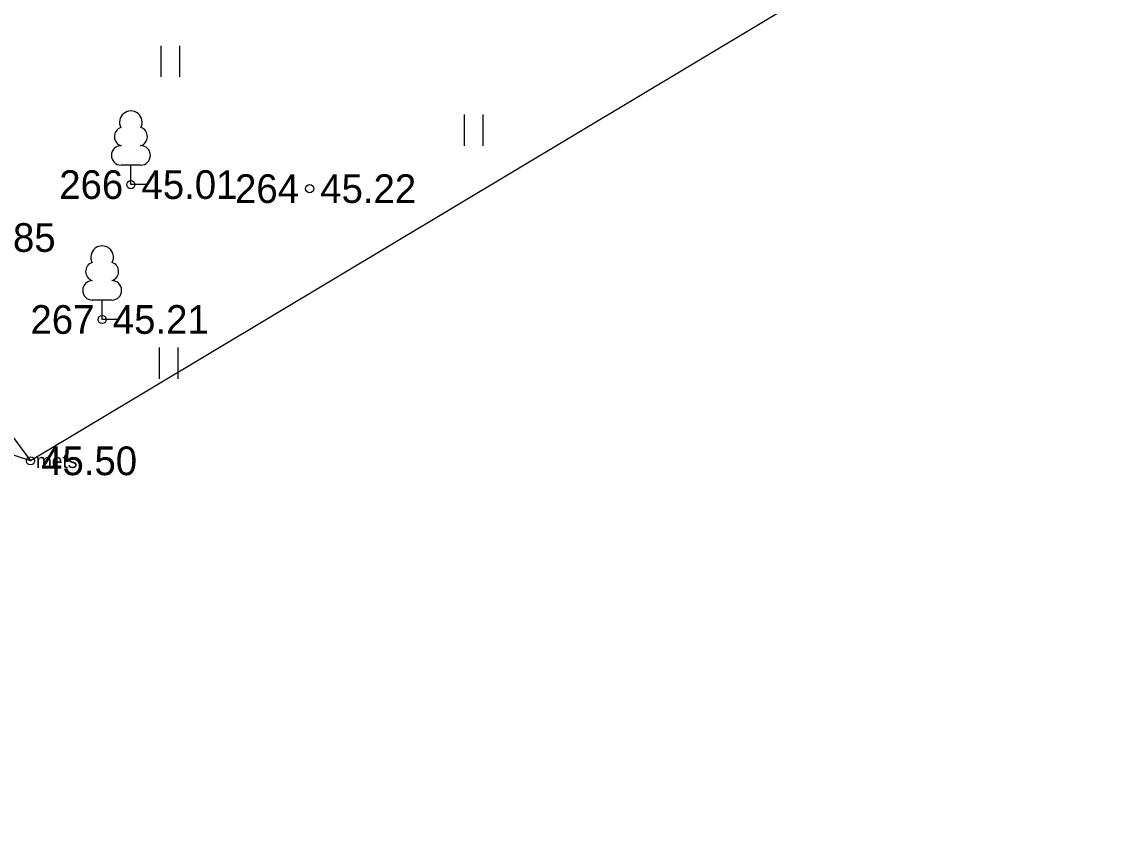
# Model space of a CAD drawing. Extents: x 505800 to 507326, y 6540058 to 6542128.
# Drawn here: x 506360.03 to 506386.44, y 6540313.38 to 6540333.29 of the extents above; entities that cross this region are included whole.
import ezdxf

# ---------------------------------------------------------------- set-up
doc = ezdxf.new("R2010")
doc.units = 0
for name, color, linetype in [('HALJASTUS', 7, 'Continuous'), ('KORGUS-EH2000', 7, 'Continuous'), ('MAAMUDEL', 7, 'Continuous'), ('MOOTKORG-EH2000', 7, 'Continuous'), ('MOOTMPUNKT', 7, 'Continuous'), ('MOOTNR', 7, 'Continuous'), ('MOOTPIIR', 7, 'Continuous'), ('PUU', 7, 'Continuous')]:
    doc.layers.add(name, color=color, linetype=linetype)

msp = doc.modelspace()

# ---------------------------------------------------------------- linework, layer by layer
at = {"layer": 'HALJASTUS'}
for p, q in [((506363.43, 6540332.702), (506363.43, 6540331.941)), ((506363.885, 6540332.702), (506363.885, 6540331.941)), ((506370.837, 6540331.019), (506370.837, 6540330.258)), ((506371.292, 6540331.019), (506371.292, 6540330.258)), ((506363.39, 6540325.331), (506363.39, 6540324.57)), ((506363.845, 6540325.331), (506363.845, 6540324.57))]:
    msp.add_line(p, q, dxfattribs=at)
msp.add_lwpolyline([(506306.227, 6540291.97), (506307.537, 6540296.92), (506309.208, 6540301.088), (506313.28, 6540303.838), (506321.716, 6540309.454), (506329.329, 6540313.144), (506334.711, 6540318.885), (506344.435, 6540326.129), (506351.88, 6540331.712), (506354.071, 6540331.501), (506356.847, 6540327.167), (506360.247, 6540322.568)], dxfattribs=at)
at = {"layer": 'KORGUS-EH2000'}
for centre in [(506362.697, 6540329.311), (506367.061, 6540329.212), (506361.996, 6540326.018), (506360.247, 6540322.568)]:
    msp.add_circle(centre, 0.1, dxfattribs=at)
at = {"layer": 'MOOTMPUNKT'}
for centre in [(506362.697, 6540329.311), (506367.061, 6540329.212), (506361.996, 6540326.018), (506360.247, 6540322.568)]:
    msp.add_circle(centre, 0.1, dxfattribs=at)
at = {"layer": 'MOOTPIIR'}
msp.add_lwpolyline([(506495.183, 6540386.603), (506455.807, 6540378.751), (506413.936, 6540356.957), (506411.426, 6540354.112), (506402.307, 6540351.523), (506391.999, 6540341.498), (506380.901, 6540334.942), (506360.247, 6540322.568), (506353.013, 6540324.95), (506332.133, 6540309.036), (506315.598, 6540297.889), (506301.375, 6540281.904), (506292.827, 6540267.673), (506286.653, 6540264.508), (506248.469, 6540250.071)], dxfattribs=at)
at = {"layer": 'PUU'}
for p, q in [((506362.938, 6540329.786), (506362.458, 6540329.786)), ((506362.697, 6540329.311), (506362.697, 6540329.786)), ((506363.078, 6540329.311), (506362.697, 6540329.311)), ((506362.236, 6540326.493), (506361.756, 6540326.493)), ((506361.996, 6540326.018), (506361.996, 6540326.493)), ((506362.376, 6540326.018), (506361.996, 6540326.018))]:
    msp.add_line(p, q, dxfattribs=at)
for centre, radius, start, end in [((506362.697, 6540330.831), 0.277, 332.5799, 207.4201), ((506362.527, 6540330.484), 0.233, 109.0217, 253.1415), ((506362.868, 6540330.484), 0.233, 286.8508, 70.9859), ((506362.46, 6540330.024), 0.238, 90.0016, 269.3953), ((506362.935, 6540330.024), 0.238, 270.6047, 89.9984), ((506361.996, 6540327.538), 0.277, 332.5799, 207.4201), ((506361.826, 6540327.19), 0.233, 109.0217, 253.1415), ((506362.166, 6540327.19), 0.233, 286.8508, 70.9859), ((506361.759, 6540326.73), 0.238, 90.0016, 269.3953), ((506362.234, 6540326.73), 0.238, 270.6047, 89.9984)]:
    msp.add_arc(centre, radius, start, end, dxfattribs=at)

# ---------------------------------------------------------------- texts
at = {"layer": 'KORGUS-EH2000'}
for s, p in [(' 45.22', (506367.061, 6540328.862)), (' 45.50', (506360.247, 6540322.218))]:
    msp.add_text(s, height=0.7, dxfattribs=at).set_placement(p)
at = {"layer": 'MAAMUDEL'}
msp.add_text(' mets', height=0.35, dxfattribs=at).set_placement((506360.247, 6540322.393))
at = {"layer": 'MOOTKORG-EH2000'}
for s, p in [(' 45.01', (506362.697, 6540328.961)), (' 45.22', (506367.061, 6540328.862)), (' 44.85', (506358.257, 6540327.669)), (' 45.21', (506361.996, 6540325.668)), (' 45.50', (506360.247, 6540322.218))]:
    msp.add_text(s, height=0.7, dxfattribs=at).set_placement(p)
at = {"layer": 'MOOTNR'}
for s, p in [('266 ', (506360.948, 6540328.961)), ('264 ', (506365.241, 6540328.862)), ('267 ', (506360.246, 6540325.668))]:
    msp.add_text(s, height=0.7, dxfattribs=at).set_placement(p)

doc.saveas('drawing.dxf')
